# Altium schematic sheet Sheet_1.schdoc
size 309 x 156 mm
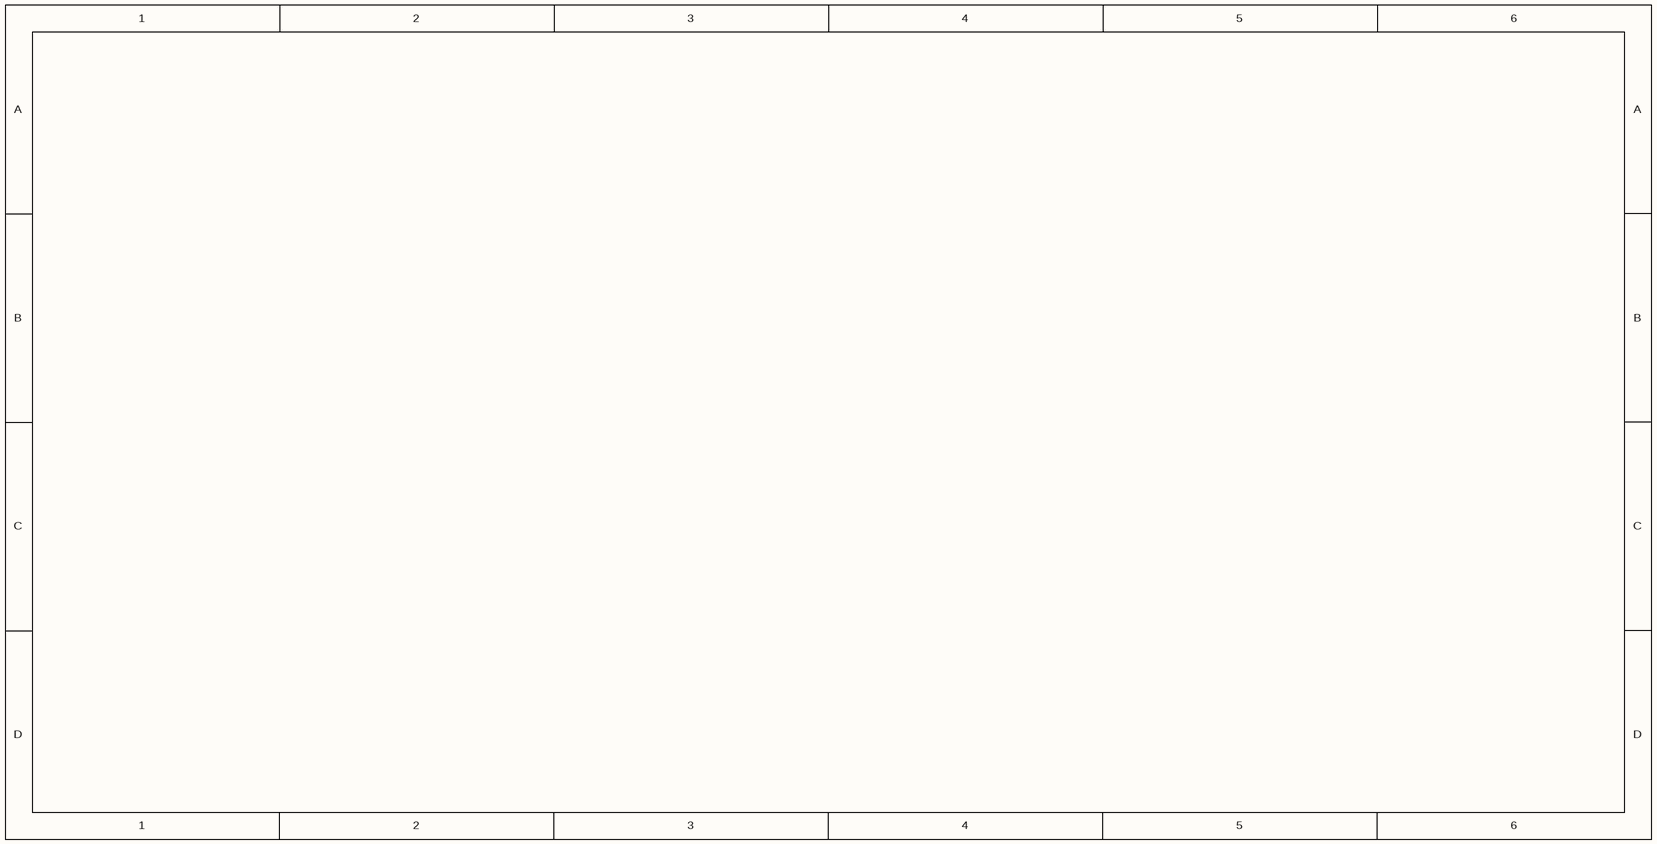
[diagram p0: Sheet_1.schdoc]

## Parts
C1  1uF  [CAP-SMD_L3.5-W2.8-R-RD]
C2  100nF  [1206]
C3  10PF  [0603]
C4  10PF  [0603]
C5  100nF  [1206]
C10  10uF  [CAP-SMD_L3.5-W2.8-R-RD]
C11  10uF  [CAP-SMD_L3.5-W2.8-R-RD]
C12  5PF  [0603]
C13  5PF  [0603]
C14  100nF  [1206]
C16  100nF  [1206]
C19  100nF  [1206]
C20  100nF  [1206]
C21  10uF  [CAP-SMD_L3.5-W2.8-R-RD]
C22  10uF  [CAP-SMD_L3.5-W2.8-R-RD]
C23  10uF  [CAP-SMD_L3.5-W2.8-R-RD]
C24  100nF  [1206]
C25  10uF  [CAP-SMD_L3.5-W2.8-R-RD]
D2  LED  [LED1206-R-RD]
J1  POWER_JACK  [POWER_JACK_SMD_OVERPASTE_TOE]
L2  4.7uH  [L0805]
R1  4.7K  [R_2512]
R2  4.7K  [R_2512]
R3  10k  [R1206]
R4  10k  [R1206]
R5  100  [R1206]
U1  STM32F103CBT6  [LQFP-48_L7.0-W7.0-P0.50-LS9.0-BL]
U3  HEADER6*1  [HEADER_6*1]  (value not drawn)
U4  AMS1117-3.3V  [SOT-223-3_L6.5-W3.4-P2.30-LS7.0-BR]
U5  AMS1117-5V  [SOT-223-3_L6.5-W3.4-P2.30-LS7.0-BR]
X1  8MHz  [HC-49US-SMD]
X2  Seiko  [OSC-TH_BD2.0-P0.50]

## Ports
I2C_SCL (in), I2C_SDA (in), LORA_DIO0 (in), LORA_MISO (in), LORA_MOSI (in), LORA_NSS (in), LORA_RST (in), LORA_SCK (in), NRST (in), SWCLK (in), SWDIO (in), ULTRA SONIC1_ECHO (in), ULTRA SONIC1_TRIG (in), ULTRA SONIC2_ECHO (in), ULTRA SONIC2_TRIG (in)

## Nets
+3.3V: C21.1 C22.1 L2.2 R1.2 R2.2 R5.1 U1.1(VBAT) U1.24(VDD_1) U1.36(VDD_2) U1.48(VDD_3) U3.3 U4.2(Vout) U4.4(Vout)
+5V: C10.1 C11.1 C23.1 U3.6 U4.3(Vin) U5.2(Vout) U5.4(Vout)
GND: C1.2 C10.2 C11.2 C21.2 C22.2 C23.2 C25.2 D2.2(K) J1.GND(GNDBREAK) J1.P$4(GND) R3.1 R4.1 U1.8(VSS_A) U1.23(VSS_1) U1.35(VSS_2) U1.47(VSS_3) U3.5 U4.1(GND/ADJ) U5.1(GND/ADJ)
VCC: C25.1 J1.VIN0(PWR) U5.3(Vin)
I2C_SCL: R2.1 U1.42(PB6I2C1_SCLTIM4_CH1) ; port I2C_SCL
I2C_SDA: R1.1 U1.43(PB7I2C1_SDATIM4_CH2) ; port I2C_SDA
LORA_DIO0: U1.18(PB0ADC12_IN8TIM3_CH3) ; port LORA_DIO0
LORA_MISO: U1.16(PA6SPI1_MISOADC12_IN6TIM3_CH1) ; port LORA_MISO
LORA_MOSI: U1.17(PA7SPI1_MOSIADC12_IN7TIM3_CH2) ; port LORA_MOSI
LORA_NSS: U1.14(PA4SPI1_NSSUSART2_CKADC12_IN4) ; port LORA_NSS
LORA_RST: U1.31(PA10USART1_RXTIM1_CH3) ; port LORA_RST
LORA_SCK: U1.15(PA5SPI1_SCKADC12_IN5) ; port LORA_SCK
NRST: U1.7(NRST) U3.1 ; port NRST
SWCLK: U1.37(PA14JTCKSWCLK) U3.2 ; port SWCLK
SWDIO: U1.34(PA13JTMSSWDIO) U3.4 ; port SWDIO
ULTRA SONIC1_ECHO: U1.29(PA8USART1_CKTIM1_CH1MCO) ; port ULTRA SONIC1_ECHO
ULTRA SONIC1_TRIG: U1.33(PA12USART1_RTSCAN_TXTIM1_ETRUSBDP) ; port ULTRA SONIC1_TRIG
ULTRA SONIC2_ECHO: U1.32(PA11USART1_CTSCAN_RXTIM1_CH4USBDM) ; port ULTRA SONIC2_ECHO
ULTRA SONIC2_TRIG: U1.27(PB14SPI2_MISOUSART3_RTSTIM1_CH2N) ; port ULTRA SONIC2_TRIG
NetC1_1: C1.1 L2.1 U1.9(VDD_A)
NetD2_1: D2.1(A) R5.2
NetR3_2: R3.2 U1.44(BOOT0)
NetR4_2: R4.2 U1.20(PB2BOOT1)
NetU1_3: U1.3(PC14-OSC32_IN) X2.2(OSC2)
NetU1_4: U1.4(PC15-OSC32_OUT) X2.1(OSC1)
NetU1_5: U1.5(PD0-OSC_IN) X1.1
NetU1_6: U1.6(PD0-OSC_OUT) X1.2

Not connected (* = marked no-connect by the designer): U1 2(PC13-TAMPER-RTC)* 10(PA0_WKUPUSART2_CTSADC12_IN0TIM2_CH1_ETR)* 11(PA1USART2_RTSADC12_IN1TIM2_CH2)* 12(PA2USART2_TXADC12_IN2TIM2_CH3)* 13(PA3USART2_RXADC12_IN3TIM2_CH4)* 19(PB1ADC12_IN9TIM3_CH4)* 21(PB10I2C2_SCLUSART3_TX)* 22(PB11I2C2_SDAUSART3_RX-)* 25(PB12SPI2_NSSI2C2_SMBAUSART3_CKTIM1_BKIN)* 26(PB13SPI2_SCKUSART3_CTSTIM1_CH1N)* 28(PB15SPI2_MOSITIM1_CH3N)* 30(PA9USART1_TXTIM1_CH2)* 38(PA15JTDI)* 39(PB3JTDO)* 40(PB4NJTRST)* 41(PB5I2C1_SMBA)* 45(PB8TIM4_CH3)* 46(PB9TIM4_CH4)*

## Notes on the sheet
- Labels drawn without touching a wire or pin: GND

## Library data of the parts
C1 = 1uF: BOM_Manufacturer: Shenzhen Zhenhua XinYun Elec; BOM_Manufacturer Part: CA45-B-10V-100uF-M; nameAlias: Capacitance; Contributor: LCSC; SMT Type: Extend
C2 C5 C14 C16 C19 C20 C24 = 100nF: BOM_Manufacturer: HEC; BOM_Manufacturer Part: C1206X224K251T 3K; nameAlias: Capacitance
C3 C4 = 10PF: Contributor: dennieschu
C10 C11 C21-C23 C25 = 10uF: BOM_Manufacturer: Shenzhen Zhenhua XinYun Elec; BOM_Manufacturer Part: CA45-B-10V-100uF-M; nameAlias: Capacitance; Contributor: LCSC; SMT Type: Extend
C12 C13 = 5PF: Contributor: dennieschu
D2 = LED: BOM_Manufacturer: KENTO; BOM_Manufacturer Part: KT-1206Red LED; SMT Type: Extend
J1 = POWER_JACK: Contributor: SparkFun
L2 = 4.7uH: BOM_Manufacturer: Prosperity Dielectrics; BOM_Manufacturer Part: 0805F-4R7K-1LRH; nameAlias: Inductance; Contributor: LCSC
R1 R2 = 4.7K: BOM_Manufacturer: LIZ Elec; BOM_Manufacturer Part: CR2512J10912G; nameAlias: Resistance (Ohms); Contributor: LCSC
R3 R4 = 10k: BOM_Manufacturer: Ever Ohms Tech; BOM_Manufacturer Part: QR1206J100RP05; nameAlias: Resistance (Ohms); Contributor: LCSC
R5 = 100: BOM_Manufacturer: Ever Ohms Tech; BOM_Manufacturer Part: QR1206J100RP05; nameAlias: Resistance (Ohms); Contributor: LCSC
U1 = STM32F103CBT6: BOM_Manufacturer: STMicroelectronics; SMT Type: Basic
U3 = HEADER6*1: Contributor: mhmd2c
U4 = AMS1117-3.3V: BOM_Manufacturer: AMS; sourceId: dwIGgezVh; SMT Type: Basic
U5 = AMS1117-5V: BOM_Manufacturer: AMS; BOM_Manufacturer Part: AMS1117-3.3; sourceId: dwIGgezVh; SMT Type: Basic
X1 = 8MHz: Contributor: Danensago
X2 = Seiko: BOM_Manufacturer Part: VT-200-F-32.768kHz-20PPM-12.5pF; nameAlias: Value; Contributor: LCSC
